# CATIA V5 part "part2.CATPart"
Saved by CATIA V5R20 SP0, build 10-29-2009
Part number: UFO底座1
Bounding box of the stored display mesh (mm): x -45 to 45, y -45 to 44.964, z -60 to 0
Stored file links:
  C:\Users\16057\Documents\180511420 创意设计\part2.CATPart
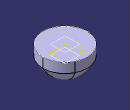
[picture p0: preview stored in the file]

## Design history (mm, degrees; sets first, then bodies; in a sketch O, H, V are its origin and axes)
Body1 (main body)
  Plane1: type Offset, RefPlane xy-plane, Offset 20, reversed
  Plane2: type Offset, RefPlane Plane1, Offset 20, reversed
  Sketch1 on Plane2, origin (0, 0, -40), H (1, 0, 0), V (0, 1, 0)
    circle A1 centre (0, 0) radius 30
    radius A1 = 30
  Sketch2 on Plane1, origin (0, 0, -20), H (1, 0, 0), V (0, 1, 0)
    circle A1 centre (0, 0) radius 45
    radius A1 = 45
  Sketch3 on xy-plane, origin (0, 0, 0), H (1, 0, 0), V (0, 1, 0)
    circle A1 centre (0, 0) radius 45
    radius A1 = 45
  Plane3: type Offset, RefPlane Plane2, Offset 20, reversed
  Sketch4 on Plane3, origin (0, 0, -60), H (1, 0, 0), V (0, 1, 0)
    circle A1 centre (0, 0) radius 0.05
    radius A1 = 0.05
  Loft1: solid, Sections (Sketch4; Sketch1; Sketch2)
  Pad1: profile face of Loft1, direction along Plane1, length 20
